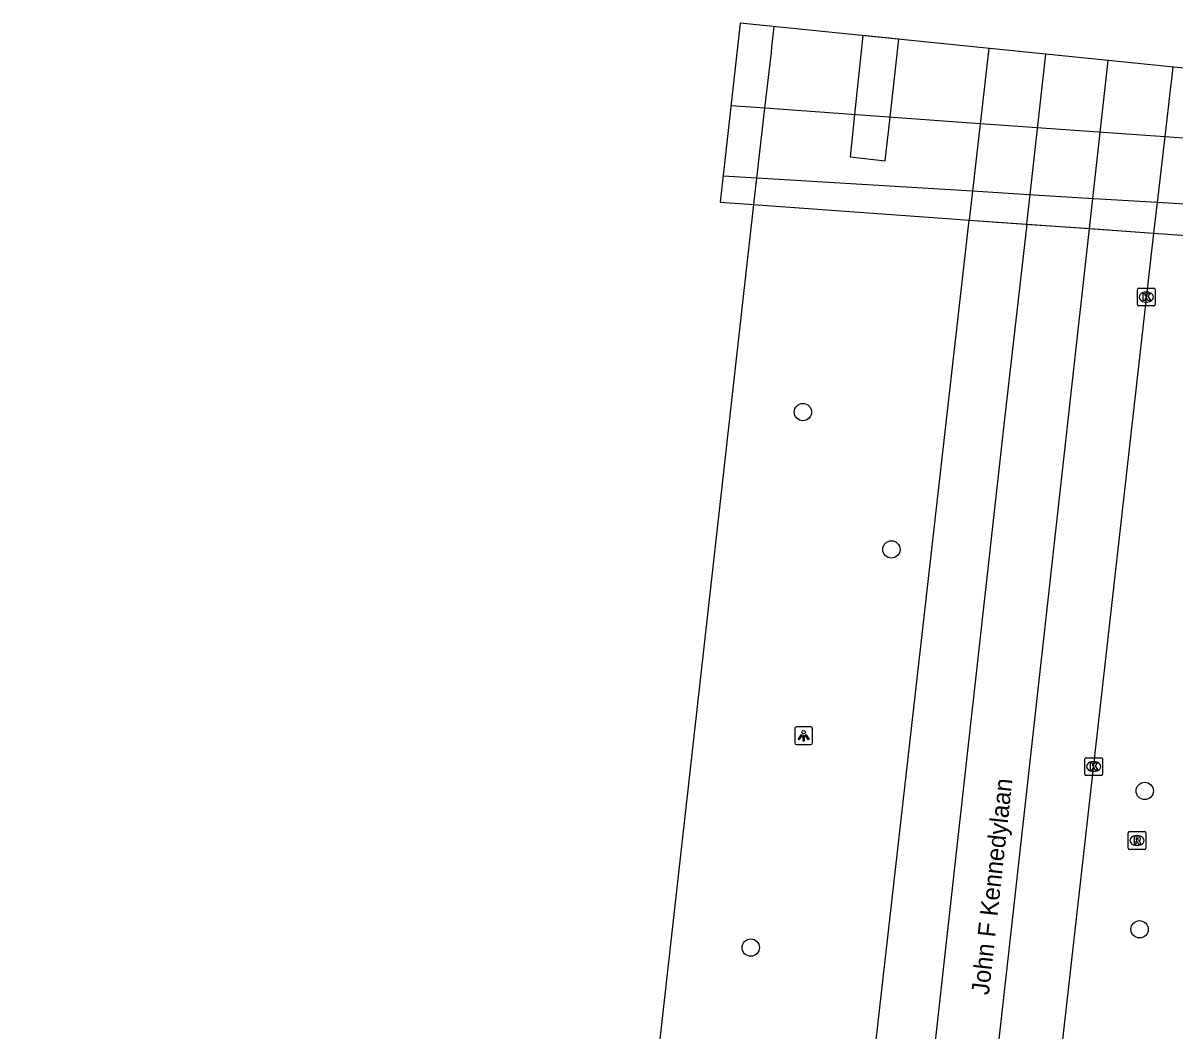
# Model space of a CAD drawing. Extents: x 161928 to 163055, y 386475 to 387428.
# Drawn here: x 161985.6 to 162050.7, y 387371.6 to 387428.5 of the extents above; entities that cross this region are included whole.
import ezdxf

# ---------------------------------------------------------------- set-up
doc = ezdxf.new("R2010")
doc.units = 0
for name, color, linetype in [('IMGEO_Boom', 7, 'Continuous'), ('IMGEO_Dek', 7, 'Continuous'), ('IMGEO_Fietspad_open', 7, 'Continuous'), ('IMGEO_Hek', 7, 'Continuous'), ('IMGEO_Kolk', 7, 'Continuous'), ('IMGEO_Lichtpunt', 7, 'Continuous'), ('IMGEO_Openbare_ruimte_label', 7, 'Continuous'), ('IMGEO_Pijler', 7, 'Continuous'), ('IMGEO_Rijbaan_lokaal_gesloten', 7, 'Continuous'), ('IMGEO_Rijbaan_regionaal_gesloten', 7, 'Continuous'), ('IMGEO_Rioolput', 7, 'Continuous')]:
    doc.layers.add(name, color=color, linetype=linetype)

msp = doc.modelspace()

# ---------------------------------------------------------------- linework, layer by layer
at = {"layer": 'IMGEO_Boom'}
for centre in [(162029.665, 387406.503), (162034.663, 387398.753), (162048.963, 387385.13), (162048.669, 387377.318), (162026.723, 387376.289)]:
    msp.add_circle(centre, 0.489, dxfattribs=at)
at = {"layer": 'IMGEO_Dek'}
msp.add_lwpolyline([(162026.126, 387428.46), (162024.993, 387418.348), (162026.896, 387418.212), (162027.894, 387418.141), (162038.051, 387417.416), (162039.047, 387417.345), (162042.496, 387417.099), (162045.892, 387416.857), (162049.451, 387416.603), (162057.505, 387416.029), (162065.215, 387415.478), (162065.381, 387417.232), (162065.646, 387420.031), (162065.722, 387420.909), (162065.983, 387424.414)], close=True, dxfattribs=at)
at = {"layer": 'IMGEO_Fietspad_open'}
msp.add_lwpolyline([(162065.381, 387417.232), (162061.851, 387417.5), (162057.7, 387417.848), (162049.655, 387418.334), (162046.095, 387418.549), (162042.707, 387418.754), (162039.233, 387418.964), (162027.067, 387419.699), (162025.157, 387419.814)], dxfattribs=at)
at = {"layer": 'IMGEO_Hek'}
for points in [[(162024.993, 387418.348), (162026.896, 387418.212)], [(162026.896, 387418.212), (162027.894, 387418.141)], [(162027.894, 387418.141), (162038.051, 387417.416)], [(162038.051, 387417.416), (162039.047, 387417.345)], [(162039.047, 387417.345), (162042.496, 387417.099)], [(162042.496, 387417.099), (162045.892, 387416.857)], [(162045.892, 387416.857), (162049.451, 387416.603)], [(162049.451, 387416.603), (162057.505, 387416.029)]]:
    msp.add_lwpolyline(points, dxfattribs=at)
at = {"layer": 'IMGEO_Kolk'}
for p, q in [((162048.622, 387413.496), (162049.474, 387413.496)), ((162048.547, 387412.57), (162048.547, 387413.422)), ((162049.035, 387413.276), (162049.06, 387413.276)), ((162049.548, 387413.422), (162049.548, 387412.57)), ((162049.474, 387412.496), (162048.622, 387412.496)), ((162049.058, 387412.716), (162049.033, 387412.716)), ((162045.574, 387386.078), (162045.574, 387386.93)), ((162045.649, 387387.004), (162046.501, 387387.004)), ((162046.062, 387386.784), (162046.087, 387386.784)), ((162046.575, 387386.93), (162046.575, 387386.078)), ((162046.085, 387386.224), (162046.06, 387386.224)), ((162046.501, 387386.004), (162045.649, 387386.004))]:
    msp.add_line(p, q, dxfattribs=at)
for points in [[(162048.622, 387413.496), (162049.474, 387413.496)], [(162048.547, 387412.57), (162048.547, 387413.422)], [(162048.868, 387413.196), (162048.991, 387413.196), (162048.991, 387413.045), (162049.121, 387413.196), (162049.285, 387413.196), (162049.139, 387413.045), (162049.292, 387412.796), (162049.14, 387412.796), (162049.055, 387412.96), (162048.991, 387412.893), (162048.991, 387412.796), (162048.868, 387412.796), (162048.868, 387413.196)], [(162049.548, 387413.422), (162049.548, 387412.57)], [(162049.474, 387412.496), (162048.622, 387412.496)], [(162045.574, 387386.078), (162045.574, 387386.93)], [(162045.649, 387387.004), (162046.501, 387387.004)], [(162046.575, 387386.93), (162046.575, 387386.078)], [(162045.895, 387386.704), (162046.018, 387386.704), (162046.018, 387386.553), (162046.148, 387386.704), (162046.312, 387386.704), (162046.166, 387386.553), (162046.319, 387386.304), (162046.167, 387386.304), (162046.082, 387386.468), (162046.018, 387386.401), (162046.018, 387386.304), (162045.895, 387386.304), (162045.895, 387386.704)], [(162046.501, 387386.004), (162045.649, 387386.004)]]:
    msp.add_lwpolyline(points, dxfattribs=at)
for centre, start, end in [((162048.624, 387413.42), 91.55205, 178.44795), ((162048.624, 387413.42), 91.55205, 178.44795), ((162049.472, 387413.42), 1.55205, 88.44795), ((162049.472, 387413.42), 1.55205, 88.44795), ((162048.624, 387412.572), 181.55205, 268.44795), ((162048.624, 387412.572), 181.55205, 268.44795), ((162049.472, 387412.572), 271.55205, 358.44795), ((162049.472, 387412.572), 271.55205, 358.44795), ((162045.651, 387386.928), 91.55205, 178.44795), ((162045.651, 387386.928), 91.55205, 178.44795), ((162046.499, 387386.928), 1.55205, 88.44795), ((162046.499, 387386.928), 1.55205, 88.44795), ((162045.651, 387386.08), 181.55205, 268.44795), ((162045.651, 387386.08), 181.55205, 268.44795), ((162046.499, 387386.08), 271.55205, 358.44795), ((162046.499, 387386.08), 271.55205, 358.44795)]:
    msp.add_arc(centre, 0.0765, start, end, dxfattribs=at)
for centre, major_axis, ratio, start_param, end_param in [((162049.034, 387412.996), (-0.387, 0.002), 0.722429, 4.712389, 7.853982), ((162049.059, 387412.996), (-0.39, 0.002), 0.717154, 1.570796, 4.712389), ((162046.061, 387386.504), (-0.387, 0.002), 0.722429, 4.712389, 7.853982), ((162046.086, 387386.504), (-0.39, 0.002), 0.717154, 1.570796, 4.712389)]:
    msp.add_ellipse(centre, major_axis=major_axis, ratio=ratio, start_param=start_param, end_param=end_param, dxfattribs=at)
at = {"layer": 'IMGEO_Lichtpunt'}
for p, q in [((162030.108, 387388.737), (162029.3, 387388.737)), ((162030.108, 387388.737), (162029.3, 387388.737)), ((162029.206, 387388.642), (162029.206, 387387.835)), ((162029.206, 387388.642), (162029.206, 387387.835)), ((162030.202, 387387.835), (162030.202, 387388.642)), ((162030.202, 387387.835), (162030.202, 387388.642)), ((162029.3, 387387.741), (162030.108, 387387.741)), ((162029.3, 387387.741), (162030.108, 387387.741))]:
    msp.add_line(p, q, dxfattribs=at)
for points in [[(162029.58, 387388.306), (162029.619, 387388.278), (162029.431, 387388.016), (162029.393, 387388.043), (162029.58, 387388.306)], [(162029.682, 387388.258), (162029.729, 387388.258), (162029.729, 387387.936), (162029.682, 387387.936), (162029.682, 387388.258)], [(162029.792, 387388.278), (162029.83, 387388.305), (162030.017, 387388.043), (162029.978, 387388.015), (162029.792, 387388.278)]]:
    msp.add_lwpolyline(points, dxfattribs=at)
msp.add_circle((162029.705, 387388.44), 0.0994, dxfattribs=at)
for centre, start, end in [((162029.3, 387388.642), 90, 180), ((162029.3, 387388.642), 90, 180), ((162030.108, 387388.642), 0, 90), ((162030.108, 387388.642), 0, 90), ((162029.3, 387387.835), 180, 270), ((162029.3, 387387.835), 180, 270), ((162030.108, 387387.835), 270, 0), ((162030.108, 387387.835), 270, 360)]:
    msp.add_arc(centre, 0.0946, start, end, dxfattribs=at)
at = {"layer": 'IMGEO_Pijler'}
msp.add_lwpolyline([(162035.081, 387427.551), (162033.041, 387427.758), (162032.579, 387423.291), (162032.333, 387420.913), (162034.314, 387420.676), (162034.589, 387423.146)], close=True, dxfattribs=at)
at = {"layer": 'IMGEO_Rijbaan_lokaal_gesloten'}
msp.add_lwpolyline([(162065.722, 387420.909), (162058.089, 387421.459), (162050.09, 387422.033), (162039.67, 387422.781), (162027.523, 387423.654), (162025.603, 387423.792)], dxfattribs=at)
at = {"layer": 'IMGEO_Rijbaan_regionaal_gesloten'}
for points in [[(162026.896, 387418.212), (162027.067, 387419.699), (162027.523, 387423.654), (162027.885, 387426.807), (162027.92, 387427.114), (162028.052, 387428.264)], [(162040.156, 387427.036), (162040.026, 387425.899), (162039.684, 387422.901), (162039.67, 387422.781), (162039.233, 387418.964), (162039.047, 387417.345)], [(162042.307, 387417.112), (162043.371, 387426.709)], [(162046.882, 387426.353), (162045.829, 387416.861)], [(162050.553, 387425.98), (162050.471, 387425.278), (162050.421, 387424.855), (162050.09, 387422.033), (162049.655, 387418.334), (162049.451, 387416.603)], [(161985.65, 387049.083), (162000, 387177.371), (162006.579, 387236.694), (162008.055, 387250), (162012.98, 387294.179), (162019.411, 387351.497), (162026.896, 387418.212)], [(162024.993, 387418.348), (162026.896, 387418.212)], [(161997.606, 387047.891), (162000, 387069.001), (162009.068, 387150.514), (162018.492, 387235.226), (162020.135, 387250), (162020.419, 387252.551), (162022.337, 387269.621), (162025.462, 387297.428), (162030.762, 387344.212), (162039.047, 387417.345)], [(162039.047, 387417.345), (162042.307, 387417.112)], [(162042.307, 387417.112), (162041.019, 387405.95), (162033.924, 387342.322), (162032.583, 387330.366), (162021.925, 387234.892), (162013.785, 387162.349), (162000.892, 387047.542)], [(162045.829, 387416.861), (162041.509, 387378.17), (162037.206, 387339.705), (162025.612, 387235.81), (162025.392, 387233.155), (162020.58, 387190.135), (162019.567, 387181.129)], [(162042.307, 387417.112), (162045.829, 387416.861)], [(162045.829, 387416.861), (162049.451, 387416.603)], [(162049.451, 387416.603), (162049.432, 387416.431), (162040.565, 387337.92), (162036.024, 387297.715), (162030.975, 387252.495), (162030.701, 387250), (162029.513, 387238.867), (162028.978, 387234.387)]]:
    msp.add_lwpolyline(points, dxfattribs=at)
at = {"layer": 'IMGEO_Rioolput'}
for p, q in [((162048.021, 387381.903), (162048.021, 387382.755)), ((162048.096, 387382.829), (162048.948, 387382.829)), ((162048.509, 387382.609), (162048.534, 387382.609)), ((162049.022, 387382.755), (162049.022, 387381.903)), ((162048.948, 387381.829), (162048.096, 387381.829)), ((162048.532, 387382.049), (162048.507, 387382.049))]:
    msp.add_line(p, q, dxfattribs=at)
for points in [[(162048.021, 387381.903), (162048.021, 387382.755)], [(162048.096, 387382.829), (162048.948, 387382.829)], [(162048.61, 387382.527), (162048.358, 387382.529), (162048.358, 387382.129)], [(162048.358, 387382.129), (162048.482, 387382.129), (162048.482, 387382.291), (162048.493, 387382.291)], [(162048.536, 387382.448), (162048.482, 387382.448), (162048.482, 387382.367)], [(162048.482, 387382.367), (162048.534, 387382.367)], [(162048.54, 387382.262), (162048.611, 387382.129), (162048.751, 387382.129), (162048.686, 387382.255)], [(162049.022, 387382.755), (162049.022, 387381.903)], [(162048.948, 387381.829), (162048.096, 387381.829)]]:
    msp.add_lwpolyline(points, dxfattribs=at)
for centre, radius, start, end in [((162048.098, 387382.753), 0.0765, 91.55205, 178.44795), ((162048.098, 387382.753), 0.0765, 91.55205, 178.44795), ((162048.492, 387382.238), 0.0533, 26.02933, 88.69889), ((162048.518, 387382.556), 0.19, 274.7715, 282.96867), ((162048.542, 387382.352), 0.0964, 77.00612, 93.18647), ((162048.556, 387382.409), 0.0378, 276.66336, 79.67722), ((162048.609, 387382.417), 0.109, 350.36119, 89.41601), ((162048.607, 387382.417), 0.112, 277.58423, 350.98172), ((162048.591, 387382.202), 0.108, 29.51342, 73.79051), ((162048.946, 387382.753), 0.0765, 1.55205, 88.44795), ((162048.946, 387382.753), 0.0765, 1.55205, 88.44795), ((162048.098, 387381.905), 0.0765, 181.55205, 268.44795), ((162048.098, 387381.905), 0.0765, 181.55205, 268.44795), ((162048.946, 387381.905), 0.0765, 271.55205, 358.44795), ((162048.946, 387381.905), 0.0765, 271.55205, 358.44795)]:
    msp.add_arc(centre, radius, start, end, dxfattribs=at)
for centre, major_axis, ratio, start_param, end_param in [((162048.508, 387382.329), (-0.387, 0.002), 0.722429, 4.712389, 7.853982), ((162048.533, 387382.329), (-0.39, 0.002), 0.717154, 1.570796, 4.712389)]:
    msp.add_ellipse(centre, major_axis=major_axis, ratio=ratio, start_param=start_param, end_param=end_param, dxfattribs=at)

# ---------------------------------------------------------------- texts
at = {"layer": 'IMGEO_Openbare_ruimte_label'}
msp.add_text('John F Kennedylaan', height=1, rotation=83.74207, dxfattribs=at).set_placement((162040.159, 387373.587))

doc.saveas('drawing.dxf')
